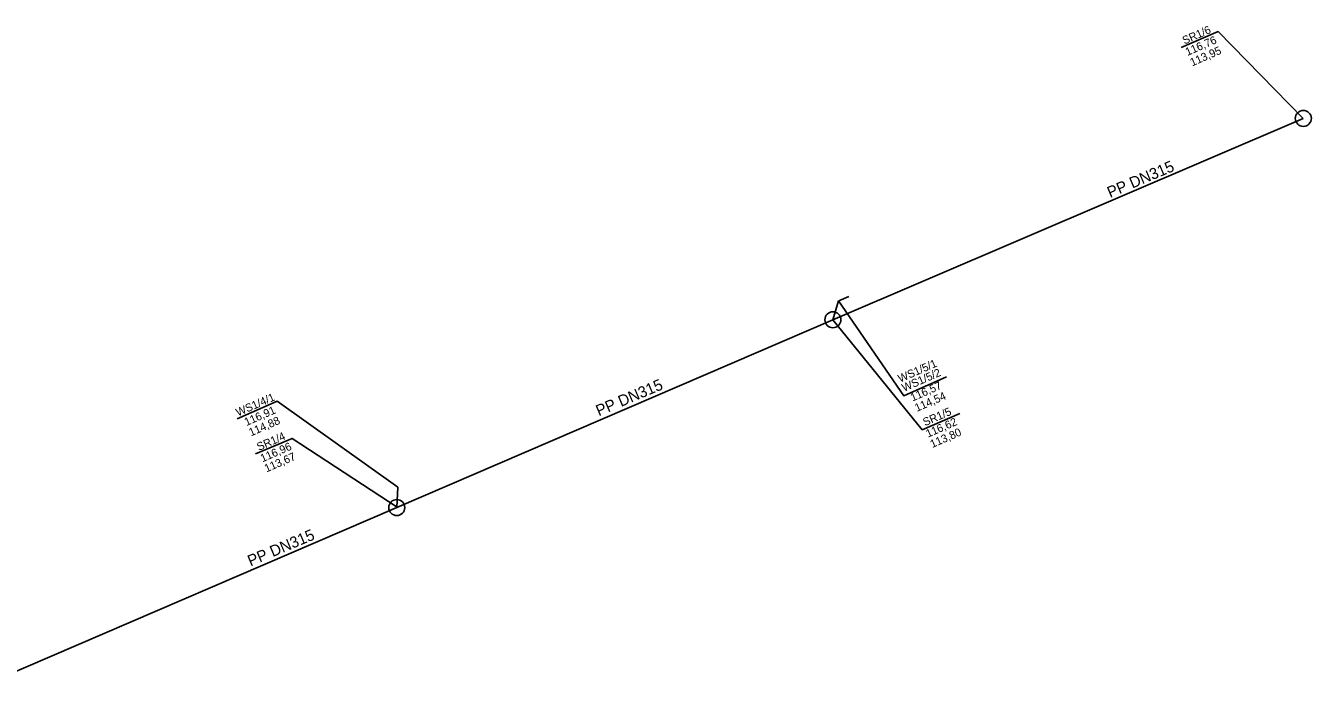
# Model space of a CAD drawing. Extents: x 7499288 to 7500494, y 5768505 to 5769051.
# Drawn here: x 7500013.6 to 7500134.1, y 5768821.3 to 5768884.1 of the extents above; entities that cross this region are included whole.
import ezdxf

# ---------------------------------------------------------------- set-up
doc = ezdxf.new("R2010")
doc.units = 0
doc.layers.add('1_proj_kd_etap1', color=7, linetype='Continuous')
doc.layers.add('2_opisy_KD_etap1', color=7, linetype='Continuous')

msp = doc.modelspace()

# ---------------------------------------------------------------- linework, layer by layer
at = {"layer": '1_proj_kd_etap1'}
for p, q in [((7500089.22, 5768856.56), (7500133.31, 5768875.44)), ((7500089.22, 5768856.56), (7500089.76, 5768858.34)), ((7500090.71, 5768858.74), (7500089.78, 5768858.33)), ((7500048.35, 5768838.95), (7500089.22, 5768856.56)), ((7500048.35, 5768838.95), (7500048.44, 5768840.87)), ((7500007.15, 5768821.26), (7500048.35, 5768838.95))]:
    msp.add_line(p, q, dxfattribs=at)
for centre in [(7500133.31, 5768875.44), (7500089.22, 5768856.56), (7500048.35, 5768838.95)]:
    msp.add_circle(centre, 0.75, dxfattribs=at)
at = {"layer": '2_opisy_KD_etap1'}
for points in [[(7500121.85, 5768882.07), (7500125.34, 5768883.57), (7500133.31, 5768875.44)], [(7500099.88, 5768851.2), (7500095.86, 5768849.44), (7500089.76, 5768858.34)], [(7500089.22, 5768856.56), (7500097.59, 5768846.25), (7500101.11, 5768847.77)], [(7500033.38, 5768847.28), (7500037.15, 5768848.92), (7500048.44, 5768840.87)], [(7500035.12, 5768844), (7500038.53, 5768845.43), (7500048.4, 5768838.99)]]:
    msp.add_lwpolyline(points, dxfattribs=at)

# ---------------------------------------------------------------- texts
for s, height, rotation, p in [('SR1/6', 0.75, 23.5988, (7500122.17, 5768882.36)), ('116,76', 0.75, 23.5988, (7500122.45, 5768881.29)), ('113,95', 0.75, 23.5988, (7500122.89, 5768880.31)), ('PP DN315', 1.05, 22.9552, (7500115.2, 5768867.97)), ('WS1/5/1', 0.75, 23.5988, (7500095.52, 5768850.66)), ('PP DN315', 1.05, 22.9552, (7500067.28, 5768847.5)), ('WS1/5/2', 0.75, 23.5988, (7500095.89, 5768849.8)), ('116,57', 0.75, 23.5988, (7500096.68, 5768848.89)), ('114,54', 0.75, 23.5988, (7500097.09, 5768847.92)), ('WS1/4/1', 0.75, 23.5988, (7500033.47, 5768847.49)), ('116,91', 0.75, 23.5988, (7500034.26, 5768846.59)), ('114,88', 0.75, 23.5988, (7500034.68, 5768845.62)), ('SR1/5', 0.75, 23.5988, (7500097.85, 5768846.57)), ('116,62', 0.75, 23.5988, (7500098.13, 5768845.5)), ('113,80', 0.75, 23.5988, (7500098.53, 5768844.53)), ('SR1/4', 0.75, 23.5988, (7500035.43, 5768844.26)), ('116,96', 0.75, 23.5988, (7500035.76, 5768843.19)), ('113,67', 0.75, 23.5988, (7500036.14, 5768842.24)), ('PP DN315', 1.05, 22.9552, (7500034.64, 5768833.42))]:
    msp.add_text(s, height=height, rotation=rotation, dxfattribs=at).set_placement(p)

doc.saveas('drawing.dxf')
